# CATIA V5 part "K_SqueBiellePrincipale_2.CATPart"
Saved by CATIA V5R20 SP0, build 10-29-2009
Part number: Squelette_bielle_principale_2
Publications: "Plan_bielle_principale", "Axe_pivot_bielle_principale_1'", "Axe_pivot_bielle_principale_2'", "Axe_pivot_bielle_principale_3'", "Droite_bielle_principale_4", "Droite_bielle_principale_3"
Bounding box of the stored display mesh (mm): x -649.987 to -88.995, y -40 to 0, z -179.845 to -51.091
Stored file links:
  G:\Khaled_CFAO_2011\ST2M\ST2M_GR2\jcoetard\Khaled\CAD_CATIA\K_SqueBiellePrincipale_2.CATPart
  G:\Khaled_CFAO_2011\ST2M\ST2M_GR2\jcoetard\jcoetard\Maquette_jcoetard\Squelette_bielle_principale.CATPart
  G:\Khaled_CFAO_2011\ST2M\ST2M_GR2\jcoetard\Khaled\CAD_CATIA\K_Squelette.CATProduct
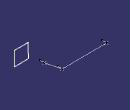
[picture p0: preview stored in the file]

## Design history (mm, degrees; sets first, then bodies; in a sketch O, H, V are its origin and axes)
Set1
  Point1 "Point.11": linked copy from another document
  Point2 "Point.8": linked copy from another document
  Point3 "Point.10": linked copy from another document
  Plane1 "Plan_bielle_motrice": linked copy from another document
Set2 "Set géométrique"
  Plane2 "Plan_bielle_principale": type Offset, RefPlane Plane1, Offset 5, reversed
  Line1 "Axe_pivot_bielle_principale_1'": type Normal, RefPoint Point1, RefSkin Plane2, Start 0, End 40
  Line2 "Axe_pivot_bielle_principale_2'": type Normal, RefPoint Point2, RefSkin Plane2, Start 0, End 40
  Line3 "Axe_pivot_bielle_principale_3'": type Normal, RefPoint Point3, RefSkin Plane2, Start 0, End 40
  Line4 "Droite_bielle_principale_3": type PtPt, FirstPoint Point1, SecondPoint Point2
  Line5 "Droite_bielle_principale_4": type PtPt, FirstPoint Point2, SecondPoint Point3
Body1 (main body)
